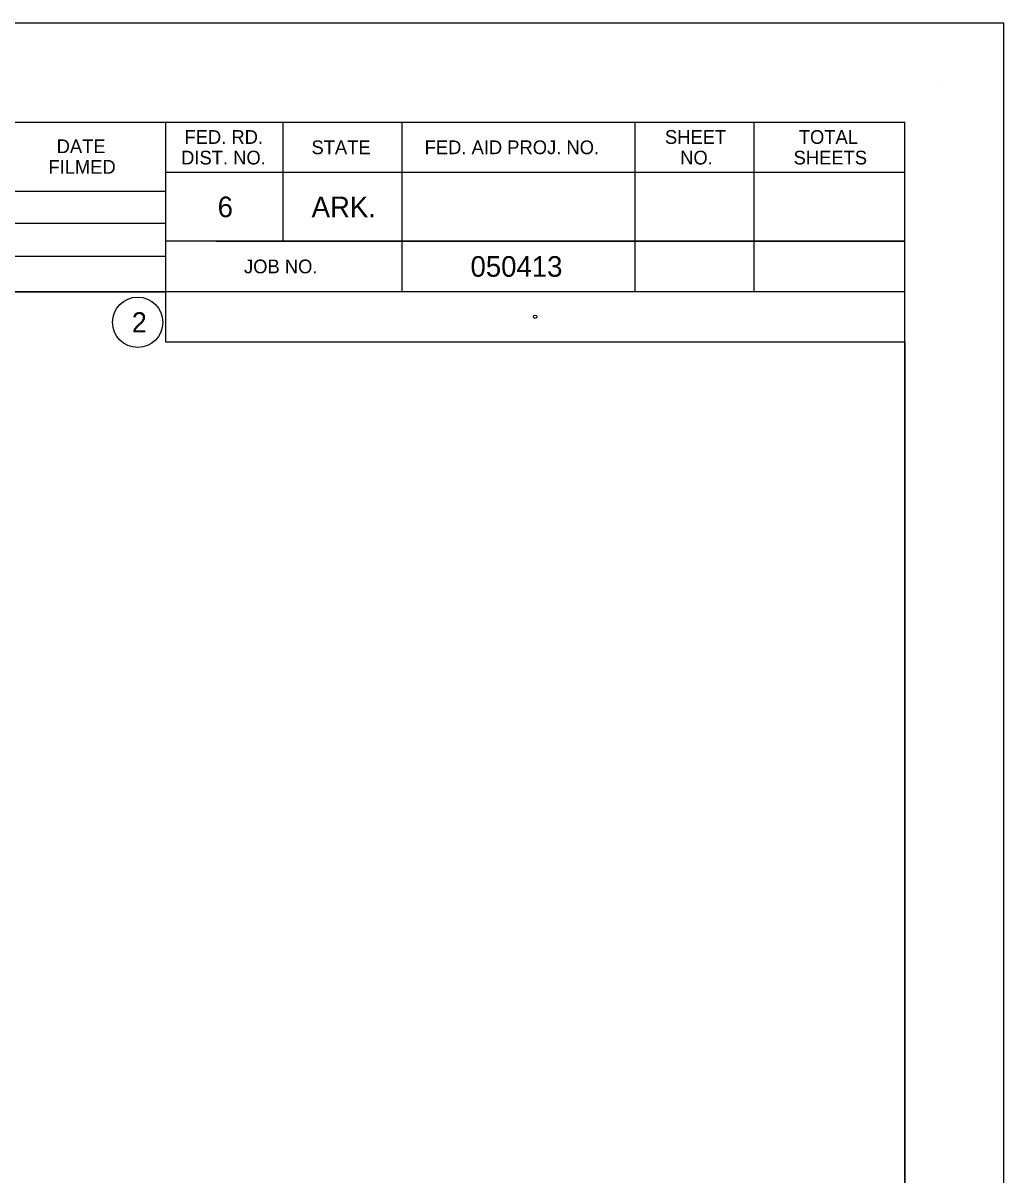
# Model space of a CAD drawing. Extents: x 0 to 38.1, y -1.4 to 22.
# Drawn here: x 28.28 to 34, y 15.29 to 22 of the extents above; entities that cross this region are included whole.
import ezdxf

# ---------------------------------------------------------------- set-up
doc = ezdxf.new("R2010")
doc.units = 0
doc.layers.add('1', color=7, linetype='Continuous')
doc.layers.add('NO PLOT CELL', color=7, linetype='Continuous')

msp = doc.modelspace()

# ---------------------------------------------------------------- linework, layer by layer
at = {"layer": '1'}
for p, q in [((33.6421, 21.6538), (33.6421, 21.6538)), ((1.516, 21.4232), (33.4232, 21.4232)), ((29.1132, 21.4232), (29.1132, 20.1432)), ((29.7972, 21.4232), (29.7972, 20.7292)), ((30.4912, 21.4232), (30.4912, 20.4352)), ((31.8492, 21.4232), (31.8492, 20.4352)), ((32.5432, 21.4232), (32.5432, 20.4352)), ((33.4232, 0.5768), (33.4232, 21.4232)), ((33.4232, 21.1292), (29.1132, 21.1292)), ((33.4232, 21.1312), (33.4232, 21.1312)), ((25.1972, 21.0212), (29.1132, 21.0212)), ((25.1972, 20.8352), (29.1132, 20.8352)), ((33.4232, 20.7292), (29.1132, 20.7292)), ((29.4092, 20.7292), (33.4232, 20.7292)), ((25.1972, 20.6412), (29.1132, 20.6412)), ((33.4232, 20.4352), (25.1972, 20.4352)), ((29.1132, 20.1432), (33.4232, 20.1432))]:
    msp.add_line(p, q, dxfattribs=at)
for points in [[(34, 22), (0, 22), (0, 0), (34, 0)], [(1.516, 0.5768), (1.516, 21.4232), (25.1972, 21.4232), (25.1972, 20.4352), (29.1132, 20.4352), (29.1132, 20.1432), (33.4232, 20.1432), (33.4232, 0.5768)]]:
    msp.add_lwpolyline(points, close=True, dxfattribs=at)
msp.add_circle((28.9518, 20.2568), 0.1467, dxfattribs=at)
at = {"layer": 'NO PLOT CELL'}
msp.add_circle((31.2682, 20.2892), 0.01, dxfattribs=at)

# ---------------------------------------------------------------- texts
at = {"layer": '1'}
for s, height, p in [('FED. RD.', 0.08, (29.2246, 21.2962)), ('SHEET', 0.08, (32.0245, 21.2962)), ('TOTAL', 0.08, (32.8043, 21.2962)), ('DATE', 0.08, (28.4797, 21.2422)), ('STATE', 0.08, (29.9647, 21.2362)), ('FED. AID PROJ. NO.', 0.08, (30.6241, 21.2362)), ('DIST. NO.', 0.08, (29.2051, 21.1762)), ('NO.', 0.08, (32.1131, 21.1762)), ('SHEETS', 0.08, (32.7741, 21.1762)), ('FILMED', 0.08, (28.4315, 21.1222)), ('6', 0.12, (29.4179, 20.8692)), ('ARK.', 0.12, (29.9656, 20.8692)), ('JOB NO.', 0.08, (29.5716, 20.5422)), ('050413', 0.12, (30.8915, 20.5222)), ('2', 0.1172, (28.9179, 20.1982))]:
    msp.add_text(s, height=height, dxfattribs=at).set_placement(p)

doc.saveas('drawing.dxf')
